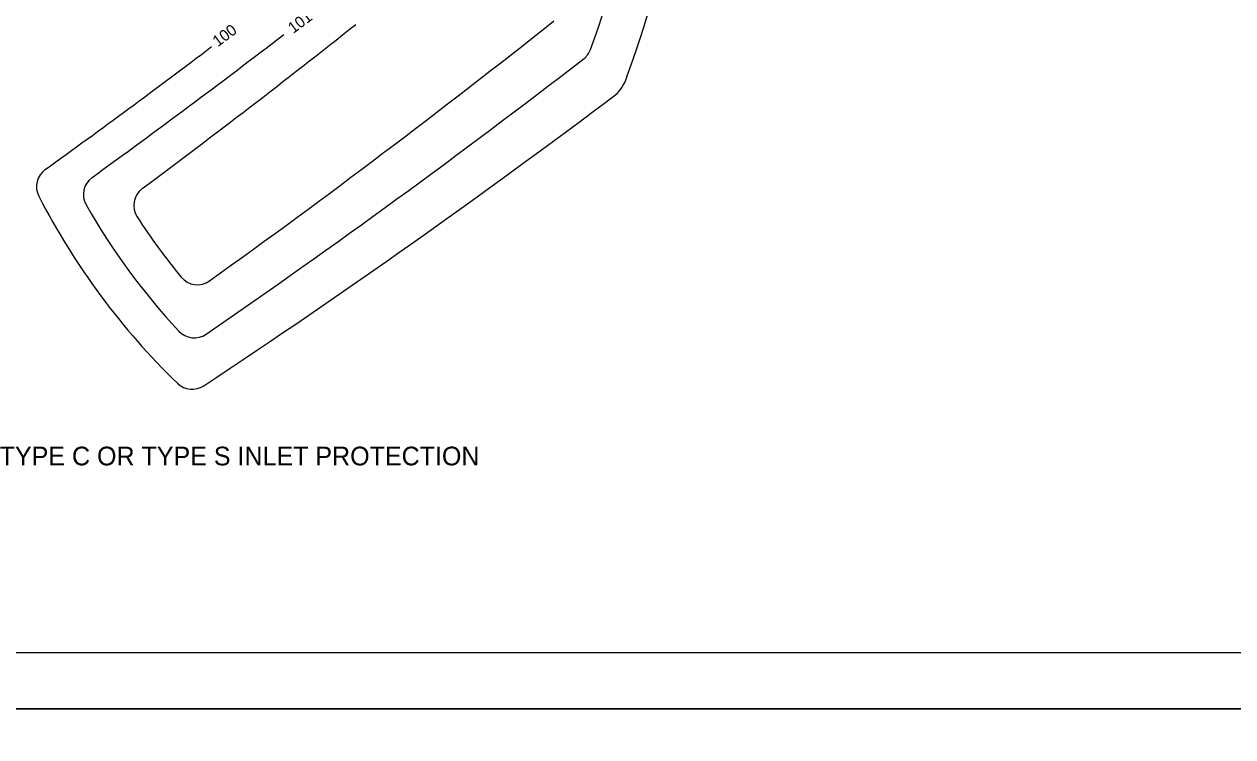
# Model space of a CAD drawing. Extents: x 636183 to 639890, y 299162 to 300538.
# Drawn here: x 636627.1 to 636949.7, y 299936.9 to 300127.2 of the extents above; entities that cross this region are included whole.
import ezdxf

# ---------------------------------------------------------------- set-up
doc = ezdxf.new("R2010")
doc.units = 0
for name, color, linetype in [('1', 7, 'Continuous'), ('Default', 7, 'Continuous'), ('PLT-BNDY', 7, 'Continuous')]:
    doc.layers.add(name, color=color, linetype=linetype)

msp = doc.modelspace()

# ---------------------------------------------------------------- linework, layer by layer
at = {"layer": '1'}
msp.add_lwpolyline([(637287.91, 299959.45), (637287.91, 300523.45), (636501.91, 300523.45), (636501.91, 299959.45), (637287.91, 299959.45), (637287.91, 299985.81), (637087.91, 299985.81), (637087.91, 300050.49), (637287.91, 300050.49), (637287.91, 300079.45), (637087.91, 300079.45), (637087.91, 299959.45), (637166.72, 299959.45), (637166.72, 299985.81), (637166.72, 299959.45), (637243.72, 299959.45), (637243.72, 299985.81), (637243.72, 299973.49), (637287.91, 299973.49)], dxfattribs=at)
at = {"layer": 'Default'}
for centre, radius, start, end in [((636561.58, 300201.79), 231.47, 339.4097, 4.4912), ((636560.94, 300198), 242.39, 339.5737, 5.462), ((635217.44, 302016.45), 2411.25, 306.70469, 308.41367), ((635327.45, 301941.55), 2316.32, 305.62348, 308.4705), ((635258.67, 302000.22), 2363.41, 305.92114, 307.47004), ((635250.78, 302005.66), 2363.41, 305.78323, 307.12227), ((636773, 300122.36), 5.62, 309.1338, 339.4097), ((635392.77, 301910.35), 2264.37, 304.50994, 307.66979), ((636776.97, 300116.56), 11.56, 316.8562, 344.1509), ((635446.06, 301887.36), 2226.58, 303.50082, 306.97937), ((636636, 300083.83), 5.62, 125.7832, 207.2261), ((636648.51, 300081.72), 5.62, 125.9211, 209.692), ((636801.83, 300169.14), 192.11, 207.2261, 225.8423), ((636661.98, 300078.78), 5.62, 126.7047, 212.8707), ((636801.83, 300169.14), 182.11, 209.692, 222.8646), ((636801.83, 300169.14), 172.12, 212.8707, 219.4888), ((636673.33, 300063.26), 5.62, 219.4888, 305.6235), ((636672.46, 300049.08), 5.62, 222.8646, 304.5099), ((636671.91, 300035.35), 5.62, 225.8423, 303.5008)]:
    msp.add_arc(centre, radius, start, end, dxfattribs=at)
at = {"layer": 'PLT-BNDY'}
for points in [[(636461.91, 300538.45), (637302.91, 300538.45), (637302.91, 299944.45), (636461.91, 299944.45)], [(636461.91, 299944.45), (637302.91, 299944.45), (637302.91, 299350.45), (636461.91, 299350.45)]]:
    msp.add_lwpolyline(points, close=True, dxfattribs=at)

# ---------------------------------------------------------------- texts
at = {"layer": 'Default'}
for s, p in [('101', (636698.92, 300124.56)), ('100', (636678.79, 300121.01))]:
    msp.add_text(s, height=2.998, rotation=36.7736, dxfattribs=at).set_placement(p)
msp.add_text('TYPE C OR TYPE S INLET PROTECTION', height=4.9967, dxfattribs=at).set_placement((636620.55, 300009.41))

doc.saveas('drawing.dxf')
